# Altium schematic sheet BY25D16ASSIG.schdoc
size 127 x 101 mm
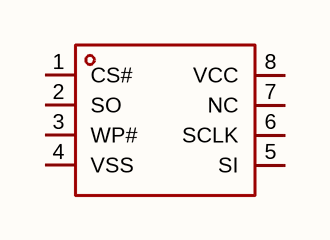
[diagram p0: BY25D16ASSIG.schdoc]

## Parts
U?  by25d16assig(t)  [SOP-8_L4.9-W3.9-P1.27-LS6.0-BL]  (value not drawn)

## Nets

Not connected (* = marked no-connect by the designer): U? 1(CS#) 2(SO) 3(WP#) 4(VSS) 5(SI) 6(SCLK) 7(NC) 8(VCC)

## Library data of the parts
U? = by25d16assig(t): 接口类型:SPI;存储容量:16Mbit;时钟频率(fc):108MHz;; Manufacturer: BOYAMICRO(博雅); AddInBom: yes; ModelId: 75c24a7891ee4dd6bdac16a7163ff87e; ModelName: SOP-8_L4.9-W3.9-P1.27-LS6.0-BL-1; ModelTransform: 192.913,236.22,0,0,0,0,-0.393,2.749,0; Interface: SPI; Memory Size: 16Mbit; Clock Frequency: 108MHz; Voltage - Supply: 2.7V~3.6V; Standby Supply Current: 5uA; Program / Erase Cycles: 100000次; Page Programming Time (Tpp): 700us; Block Erase Time(tBE): 300ms@(32KB); Data Retention - TDR (Year): 20年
